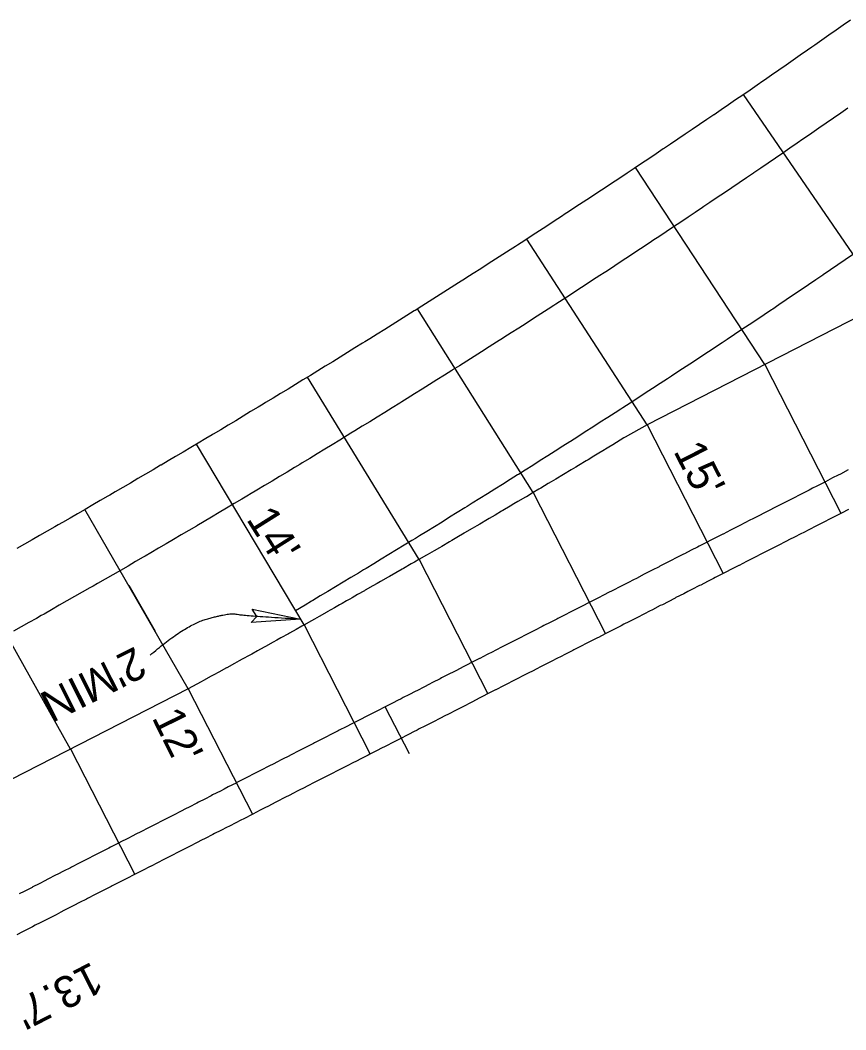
# Model space of a CAD drawing. Extents: x 2145147 to 2158018, y 137519 to 148068.
# Drawn here: x 2149689.7 to 2149783.3, y 143167.4 to 143282 of the extents above; entities that cross this region are included whole.
import ezdxf

# ---------------------------------------------------------------- set-up
doc = ezdxf.new("R2010")
doc.units = 0
for name, color, linetype in [('PR_Align_Ramp_A', 7, 'Continuous'), ('PR_Align_Ramp_F', 7, 'Continuous'), ('PR_Dimensions', 7, 'Continuous'), ('PR_Joint_Contraction', 7, 'Continuous'), ('PR_Joint_Long', 7, 'Continuous'), ('PR_Road_Concrete', 7, 'Continuous')]:
    doc.layers.add(name, color=color, linetype=linetype)

msp = doc.modelspace()

# ---------------------------------------------------------------- linework, layer by layer
at = {"layer": 'PR_Align_Ramp_A'}
msp.add_lwpolyline([(2149733.83, 143198.72), (2149731.09, 143204.07)], dxfattribs=at)
at = {"layer": 'PR_Align_Ramp_F'}
msp.add_lwpolyline([(2149705.04, 143212.62), (2149702.04, 143217.81)], dxfattribs=at)
at = {"layer": 'PR_Dimensions'}
msp.add_lwpolyline([(2149721.48, 143214.02), (2149715.88, 143213.61), (2149716.51, 143214.32), (2149715.99, 143215.14)], close=True, dxfattribs=at)
msp.add_open_spline([(2149704.41, 143209.91), (2149708.45, 143213.4), (2149713.52, 143214.74), (2149714.67, 143214.44), (2149721.48, 143214.02)], degree=2, dxfattribs=at)
at = {"layer": 'PR_Joint_Contraction'}
for p, q in [((2149785.87, 143252.94), (2149771.73, 143273.55)), ((2149774.15, 143242.92), (2149759.48, 143265.26)), ((2149760.8, 143236.08), (2149747.15, 143257.15)), ((2149747.89, 143228.38), (2149734.75, 143249.23)), ((2149774.15, 143242.92), (2149782.79, 143226.02)), ((2149734.93, 143220.78), (2149722.26, 143241.47)), ((2149760.8, 143236.08), (2149769.44, 143219.19)), ((2149721.88, 143213.35), (2149709.68, 143233.87)), ((2149747.89, 143228.38), (2149756.09, 143212.36)), ((2149708.74, 143206.1), (2149697, 143226.45)), ((2149734.93, 143220.78), (2149742.73, 143205.53)), ((2149695.38, 143199.26), (2149684.22, 143219.18)), ((2149721.88, 143213.35), (2149729.38, 143198.69)), ((2149708.74, 143206.1), (2149716.02, 143191.86)), ((2149695.39, 143199.27), (2149702.67, 143185.03))]:
    msp.add_line(p, q, dxfattribs=at)
at = {"layer": 'PR_Joint_Long'}
msp.add_line((2149708.74, 143206.1), (2149656.52, 143179.39), dxfattribs=at)
for points in [[(2149783.57, 143272.02), (2149782.76, 143271.44), (2149781.94, 143270.87), (2149781.12, 143270.31), (2149780.3, 143269.74), (2149779.47, 143269.17), (2149778.65, 143268.6), (2149778.48, 143268.48), (2149777.83, 143268.04), (2149777.01, 143267.47), (2149776.19, 143266.9), (2149775.36, 143266.34), (2149774.54, 143265.78), (2149773.71, 143265.21), (2149772.89, 143264.65), (2149772.87, 143264.64), (2149772.06, 143264.09), (2149771.24, 143263.53), (2149770.41, 143262.97), (2149769.58, 143262.41), (2149768.76, 143261.85), (2149767.93, 143261.29), (2149767.24, 143260.83), (2149767.1, 143260.74), (2149766.27, 143260.18), (2149765.44, 143259.62), (2149764.61, 143259.07), (2149763.78, 143258.52), (2149762.95, 143257.96), (2149762.12, 143257.41), (2149761.58, 143257.05), (2149761.29, 143256.86), (2149760.46, 143256.31), (2149759.62, 143255.76), (2149758.79, 143255.21), (2149757.96, 143254.66), (2149757.12, 143254.11), (2149756.29, 143253.56), (2149755.91, 143253.31), (2149755.45, 143253.01), (2149754.62, 143252.47), (2149753.78, 143251.92), (2149752.94, 143251.38), (2149752.11, 143250.83), (2149751.27, 143250.29), (2149750.86, 143250.02), (2149750.43, 143249.75), (2149750.21, 143249.6), (2149749.59, 143249.21), (2149748.75, 143248.66), (2149747.92, 143248.12), (2149747.08, 143247.58), (2149746.24, 143247.05), (2149745.39, 143246.51), (2149744.55, 143245.97), (2149744.49, 143245.93), (2149743.71, 143245.43), (2149742.87, 143244.9), (2149742.03, 143244.36), (2149741.18, 143243.83), (2149740.34, 143243.29), (2149739.5, 143242.76), (2149738.74, 143242.29), (2149738.65, 143242.23), (2149737.81, 143241.7), (2149736.96, 143241.17), (2149736.12, 143240.64), (2149735.27, 143240.11), (2149734.42, 143239.58), (2149733.57, 143239.05), (2149732.98, 143238.68), (2149732.73, 143238.52), (2149731.88, 143238), (2149731.03, 143237.47), (2149730.18, 143236.95), (2149729.33, 143236.42), (2149728.48, 143235.9), (2149727.63, 143235.38), (2149727.2, 143235.11), (2149726.78, 143234.85), (2149725.93, 143234.33), (2149725.08, 143233.81), (2149724.22, 143233.29), (2149723.37, 143232.77), (2149722.52, 143232.26), (2149721.66, 143231.74), (2149721.39, 143231.57), (2149720.81, 143231.22), (2149719.96, 143230.71), (2149719.1, 143230.19), (2149718.25, 143229.68), (2149717.39, 143229.16), (2149716.53, 143228.65), (2149715.68, 143228.14), (2149715.56, 143228.07), (2149714.82, 143227.63), (2149713.96, 143227.12), (2149713.1, 143226.61), (2149712.24, 143226.1), (2149711.39, 143225.59), (2149710.53, 143225.08), (2149709.72, 143224.6), (2149709.67, 143224.57), (2149708.81, 143224.07), (2149707.95, 143223.56), (2149707.08, 143223.06), (2149706.22, 143222.55), (2149705.36, 143222.05), (2149704.5, 143221.55), (2149703.85, 143221.17), (2149703.63, 143221.04), (2149702.77, 143220.54), (2149701.91, 143220.04), (2149701.04, 143219.54), (2149700.18, 143219.05), (2149699.31, 143218.55), (2149698.45, 143218.05), (2149697.96, 143217.77), (2149697.58, 143217.55), (2149696.71, 143217.06), (2149695.85, 143216.56), (2149694.98, 143216.07), (2149694.11, 143215.58), (2149693.24, 143215.08), (2149692.38, 143214.59), (2149692.05, 143214.41), (2149691.51, 143214.1), (2149690.64, 143213.61), (2149689.77, 143213.12), (2149688.9, 143212.63)], [(2149784.1, 143255.36), (2149783.27, 143254.79), (2149782.44, 143254.22), (2149781.6, 143253.65), (2149780.77, 143253.08), (2149780.74, 143253.06), (2149779.93, 143252.51), (2149779.1, 143251.94), (2149778.26, 143251.38), (2149777.42, 143250.81), (2149776.58, 143250.25), (2149775.75, 143249.68), (2149775.05, 143249.21), (2149774.91, 143249.12), (2149774.07, 143248.55), (2149773.23, 143247.99), (2149772.39, 143247.43), (2149771.55, 143246.87), (2149770.71, 143246.31), (2149769.87, 143245.75), (2149769.32, 143245.39), (2149769.02, 143245.19), (2149768.18, 143244.63), (2149767.34, 143244.07), (2149766.5, 143243.52), (2149765.65, 143242.96), (2149764.81, 143242.41), (2149763.96, 143241.85), (2149763.58, 143241.6), (2149763.12, 143241.3), (2149762.27, 143240.75), (2149761.43, 143240.19), (2149760.58, 143239.64), (2149759.73, 143239.09), (2149758.89, 143238.54), (2149758.47, 143238.27), (2149758.04, 143237.99), (2149757.81, 143237.84), (2149757.19, 143237.44), (2149756.34, 143236.9), (2149755.49, 143236.35), (2149754.64, 143235.8), (2149753.79, 143235.26), (2149752.94, 143234.71), (2149752.09, 143234.17), (2149752.02, 143234.12), (2149751.23, 143233.63), (2149750.38, 143233.08), (2149749.53, 143232.54), (2149748.67, 143232), (2149747.82, 143231.46), (2149746.97, 143230.92), (2149746.21, 143230.44), (2149746.11, 143230.38), (2149745.26, 143229.84), (2149744.4, 143229.31), (2149743.54, 143228.77), (2149742.69, 143228.23), (2149741.83, 143227.7), (2149740.97, 143227.17), (2149740.37, 143226.79), (2149740.11, 143226.63), (2149739.26, 143226.1), (2149738.4, 143225.57), (2149737.54, 143225.03), (2149736.68, 143224.5), (2149735.82, 143223.97), (2149734.96, 143223.45), (2149734.52, 143223.18), (2149734.09, 143222.92), (2149733.23, 143222.39), (2149732.37, 143221.86), (2149731.51, 143221.34), (2149730.64, 143220.81), (2149729.78, 143220.29), (2149728.92, 143219.76), (2149728.64, 143219.59), (2149728.05, 143219.24), (2149727.19, 143218.72), (2149726.32, 143218.2), (2149725.46, 143217.68), (2149724.59, 143217.16), (2149723.72, 143216.64), (2149722.86, 143216.12), (2149722.74, 143216.05), (2149721.99, 143215.6), (2149720.92, 143214.96)], [(2149797.26, 143254.77), (2149760.8, 143236.08)], [(2149760.8, 143236.08), (2149758.3, 143234.66), (2149758.17, 143234.58), (2149757.31, 143234.05), (2149756.9, 143233.81), (2149756.46, 143233.53), (2149755.6, 143233.01), (2149755.51, 143232.96), (2149754.74, 143232.49), (2149754.11, 143232.11), (2149753.88, 143231.98), (2149753.02, 143231.46), (2149752.71, 143231.27), (2149752.17, 143230.94), (2149751.31, 143230.43), (2149750.45, 143229.91), (2149749.9, 143229.59), (2149749.59, 143229.4), (2149748.73, 143228.88), (2149748.5, 143228.75), (2149747.87, 143228.37), (2149747.1, 143227.91), (2149747, 143227.86), (2149746.14, 143227.35), (2149745.69, 143227.08), (2149745.28, 143226.84), (2149744.42, 143226.33), (2149744.28, 143226.25), (2149743.55, 143225.82), (2149742.88, 143225.42), (2149742.69, 143225.31), (2149741.83, 143224.8), (2149741.47, 143224.59), (2149740.96, 143224.3), (2149740.1, 143223.79), (2149740.06, 143223.77), (2149739.23, 143223.28), (2149738.65, 143222.94), (2149738.37, 143222.78), (2149737.5, 143222.27), (2149737.24, 143222.12), (2149736.64, 143221.77), (2149735.83, 143221.3), (2149735.77, 143221.27), (2149734.9, 143220.77), (2149734.41, 143220.48), (2149734.04, 143220.27), (2149733.17, 143219.77), (2149733, 143219.67), (2149732.3, 143219.27), (2149731.58, 143218.86), (2149731.43, 143218.77), (2149730.56, 143218.27), (2149730.17, 143218.05), (2149729.7, 143217.78), (2149728.83, 143217.28), (2149728.75, 143217.24), (2149727.96, 143216.79), (2149727.33, 143216.43), (2149727.09, 143216.29), (2149726.71, 143216.08), (2149726.21, 143215.8), (2149725.91, 143215.62), (2149725.34, 143215.3), (2149724.49, 143214.82), (2149724.47, 143214.81), (2149723.6, 143214.32), (2149723.06, 143214.02), (2149722.73, 143213.83), (2149721.86, 143213.34), (2149721.64, 143213.22), (2149720.98, 143212.85), (2149720.22, 143212.42), (2149720.11, 143212.36), (2149719.23, 143211.88), (2149718.79, 143211.63), (2149718.36, 143211.39), (2149717.49, 143210.9), (2149717.37, 143210.84), (2149716.61, 143210.42), (2149715.94, 143210.05), (2149715.74, 143209.93), (2149714.86, 143209.45), (2149714.51, 143209.26), (2149713.98, 143208.97), (2149713.11, 143208.49), (2149713.08, 143208.47), (2149712.23, 143208), (2149711.65, 143207.69), (2149711.35, 143207.52), (2149710.47, 143207.04), (2149710.22, 143206.9), (2149708.74, 143206.1)], [(2149783.62, 143230.94), (2149782.73, 143230.48), (2149782.48, 143230.36), (2149781.84, 143230.03), (2149781.03, 143229.61), (2149780.95, 143229.57), (2149780.06, 143229.12), (2149779.58, 143228.87), (2149779.17, 143228.66), (2149778.28, 143228.2), (2149778.13, 143228.13), (2149777.39, 143227.75), (2149776.67, 143227.38), (2149776.5, 143227.29), (2149775.61, 143226.84), (2149775.22, 143226.64), (2149774.72, 143226.38), (2149773.83, 143225.93), (2149773.77, 143225.9), (2149772.94, 143225.47), (2149772.32, 143225.16), (2149772.05, 143225.02), (2149771.16, 143224.56), (2149770.87, 143224.41), (2149770.27, 143224.11), (2149769.42, 143223.67), (2149769.38, 143223.65), (2149768.48, 143223.19), (2149767.96, 143222.93), (2149767.6, 143222.74), (2149766.93, 143222.4), (2149766.71, 143222.28), (2149766.51, 143222.19), (2149765.81, 143221.83), (2149765.06, 143221.44), (2149764.92, 143221.37), (2149764.03, 143220.92), (2149763.61, 143220.7), (2149763.14, 143220.46), (2149762.25, 143220.01), (2149762.16, 143219.96), (2149761.36, 143219.55), (2149760.71, 143219.21), (2149760.47, 143219.1), (2149759.58, 143218.64), (2149759.25, 143218.47), (2149758.69, 143218.18), (2149757.8, 143217.73), (2149756.91, 143217.27), (2149756.35, 143216.99), (2149756.02, 143216.82), (2149755.13, 143216.36), (2149754.9, 143216.24), (2149754.24, 143215.91), (2149753.45, 143215.5), (2149753.35, 143215.45), (2149752.46, 143215), (2149751.99, 143214.76), (2149751.57, 143214.54), (2149750.68, 143214.09), (2149750.54, 143214.02), (2149749.79, 143213.63), (2149749.09, 143213.27), (2149748.9, 143213.17), (2149748.01, 143212.72), (2149747.64, 143212.53), (2149747.12, 143212.26), (2149746.23, 143211.81), (2149746.19, 143211.79), (2149745.34, 143211.35), (2149744.74, 143211.05), (2149744.45, 143210.9), (2149743.56, 143210.44), (2149743.28, 143210.3), (2149742.67, 143209.99), (2149741.83, 143209.56), (2149741.78, 143209.53), (2149740.89, 143209.08), (2149740.38, 143208.82), (2149740, 143208.62), (2149739.11, 143208.16), (2149738.93, 143208.07), (2149738.22, 143207.71), (2149737.48, 143207.33), (2149737.33, 143207.25), (2149736.44, 143206.8), (2149736.03, 143206.59), (2149735.55, 143206.34), (2149734.66, 143205.89), (2149734.57, 143205.85), (2149733.76, 143205.43), (2149733.12, 143205.1), (2149732.88, 143204.98), (2149732.49, 143204.78), (2149731.98, 143204.52), (2149731.67, 143204.36), (2149731.1, 143204.07), (2149730.22, 143203.62), (2149730.2, 143203.61), (2149729.31, 143203.15), (2149728.77, 143202.88), (2149728.42, 143202.7), (2149727.53, 143202.24), (2149727.32, 143202.13), (2149726.64, 143201.79), (2149725.86, 143201.39), (2149725.75, 143201.33), (2149724.86, 143200.88), (2149724.41, 143200.65), (2149723.97, 143200.42), (2149723.08, 143199.97), (2149722.96, 143199.9), (2149722.19, 143199.51), (2149721.51, 143199.16), (2149721.3, 143199.05), (2149720.41, 143198.6), (2149720.06, 143198.42), (2149719.52, 143198.14), (2149718.63, 143197.69), (2149718.6, 143197.68), (2149717.74, 143197.23), (2149717.15, 143196.93), (2149716.85, 143196.78), (2149715.96, 143196.32), (2149715.7, 143196.19), (2149715.07, 143195.87), (2149714.25, 143195.45), (2149714.18, 143195.41), (2149713.29, 143194.96), (2149712.8, 143194.7), (2149712.4, 143194.5), (2149711.51, 143194.05), (2149711.35, 143193.96), (2149710.62, 143193.59), (2149709.9, 143193.22), (2149709.73, 143193.13), (2149708.84, 143192.68), (2149708.44, 143192.48), (2149707.95, 143192.22), (2149707.06, 143191.77), (2149706.99, 143191.73), (2149706.17, 143191.31), (2149705.54, 143190.99), (2149705.28, 143190.86), (2149704.39, 143190.4), (2149704.09, 143190.25), (2149703.5, 143189.95), (2149702.64, 143189.51), (2149702.61, 143189.49), (2149701.72, 143189.04), (2149701.18, 143188.76), (2149700.83, 143188.58), (2149699.94, 143188.12), (2149699.73, 143188.02), (2149699.05, 143187.67), (2149698.28, 143187.28), (2149698.15, 143187.21), (2149697.26, 143186.76), (2149696.83, 143186.54), (2149696.38, 143186.3), (2149695.48, 143185.85), (2149695.38, 143185.79), (2149694.59, 143185.39), (2149693.93, 143185.05), (2149693.7, 143184.94), (2149692.81, 143184.48), (2149692.47, 143184.31), (2149691.92, 143184.02), (2149691.03, 143183.57), (2149691.02, 143183.56), (2149690.14, 143183.11), (2149689.57, 143182.82)]]:
    msp.add_lwpolyline(points, dxfattribs=at)
at = {"layer": 'PR_Road_Concrete'}
for points in [[(2149783.87, 143281.99), (2149783.06, 143281.42), (2149782.25, 143280.85), (2149781.43, 143280.28), (2149780.62, 143279.71), (2149779.81, 143279.14), (2149779.48, 143278.92), (2149779, 143278.58), (2149778.18, 143278.01), (2149777.37, 143277.44), (2149776.56, 143276.88), (2149775.74, 143276.31), (2149774.93, 143275.75), (2149774.11, 143275.19), (2149773.93, 143275.07), (2149773.29, 143274.62), (2149772.48, 143274.06), (2149771.66, 143273.5), (2149770.84, 143272.94), (2149770.02, 143272.38), (2149769.21, 143271.82), (2149768.39, 143271.26), (2149768.37, 143271.25), (2149767.57, 143270.71), (2149766.75, 143270.15), (2149765.93, 143269.59), (2149765.1, 143269.04), (2149764.28, 143268.48), (2149763.46, 143267.93), (2149762.77, 143267.47), (2149762.64, 143267.38), (2149761.82, 143266.82), (2149760.99, 143266.27), (2149760.17, 143265.72), (2149759.34, 143265.17), (2149758.52, 143264.62), (2149757.69, 143264.07), (2149757.16, 143263.72), (2149756.87, 143263.53), (2149756.04, 143262.98), (2149755.21, 143262.43), (2149754.39, 143261.88), (2149753.56, 143261.34), (2149752.73, 143260.8), (2149751.9, 143260.25), (2149751.52, 143260), (2149751.07, 143259.71), (2149750.24, 143259.17), (2149749.41, 143258.62), (2149748.58, 143258.08), (2149747.75, 143257.54), (2149746.92, 143257), (2149746.51, 143256.74), (2149746.09, 143256.46), (2149745.86, 143256.32), (2149745.25, 143255.93), (2149744.42, 143255.39), (2149743.59, 143254.85), (2149742.75, 143254.32), (2149741.92, 143253.78), (2149741.08, 143253.25), (2149740.25, 143252.71), (2149740.18, 143252.67), (2149739.41, 143252.18), (2149738.58, 143251.65), (2149737.74, 143251.12), (2149736.9, 143250.59), (2149736.07, 143250.06), (2149735.23, 143249.53), (2149734.48, 143249.06), (2149734.39, 143249), (2149733.55, 143248.47), (2149732.71, 143247.94), (2149731.87, 143247.42), (2149731.03, 143246.89), (2149730.19, 143246.37), (2149729.35, 143245.84), (2149728.76, 143245.48), (2149728.51, 143245.32), (2149727.66, 143244.8), (2149726.82, 143244.27), (2149725.98, 143243.75), (2149725.13, 143243.23), (2149724.29, 143242.71), (2149723.45, 143242.19), (2149723.01, 143241.93), (2149722.6, 143241.68), (2149721.75, 143241.16), (2149720.91, 143240.64), (2149720.06, 143240.13), (2149719.22, 143239.61), (2149718.37, 143239.1), (2149717.52, 143238.58), (2149717.25, 143238.42), (2149716.67, 143238.07), (2149715.82, 143237.56), (2149714.98, 143237.04), (2149714.13, 143236.53), (2149713.28, 143236.02), (2149712.43, 143235.51), (2149711.57, 143235.01), (2149711.46, 143234.94), (2149710.72, 143234.5), (2149709.87, 143233.99), (2149709.02, 143233.48), (2149708.17, 143232.98), (2149707.31, 143232.47), (2149706.46, 143231.97), (2149705.66, 143231.49), (2149705.61, 143231.47), (2149704.75, 143230.96), (2149703.9, 143230.46), (2149703.04, 143229.96), (2149702.19, 143229.46), (2149701.33, 143228.96), (2149700.47, 143228.46), (2149699.83, 143228.09), (2149699.62, 143227.96), (2149698.76, 143227.47), (2149697.9, 143226.97), (2149697.04, 143226.47), (2149696.18, 143225.98), (2149695.33, 143225.48), (2149694.47, 143224.99), (2149693.98, 143224.71), (2149693.61, 143224.5), (2149692.75, 143224), (2149691.88, 143223.51), (2149691.02, 143223.02), (2149690.16, 143222.53), (2149689.3, 143222.04)], [(2149783.66, 143226.47), (2149782.85, 143226.05), (2149782.77, 143226.01), (2149781.88, 143225.55), (2149781.4, 143225.31), (2149780.99, 143225.1), (2149780.1, 143224.64), (2149779.95, 143224.57), (2149779.21, 143224.19), (2149778.5, 143223.82), (2149778.32, 143223.73), (2149777.43, 143223.28), (2149777.04, 143223.08), (2149776.54, 143222.82), (2149775.65, 143222.37), (2149775.59, 143222.34), (2149774.76, 143221.91), (2149774.14, 143221.6), (2149773.87, 143221.46), (2149772.98, 143221), (2149772.69, 143220.85), (2149772.09, 143220.55), (2149771.24, 143220.11), (2149771.2, 143220.09), (2149770.31, 143219.63), (2149769.79, 143219.37), (2149769.42, 143219.18), (2149768.75, 143218.84), (2149768.53, 143218.72), (2149768.33, 143218.62), (2149767.64, 143218.27), (2149766.88, 143217.88), (2149766.75, 143217.81), (2149765.86, 143217.36), (2149765.43, 143217.14), (2149764.97, 143216.9), (2149764.07, 143216.45), (2149763.98, 143216.4), (2149763.19, 143215.99), (2149762.53, 143215.65), (2149762.29, 143215.54), (2149761.4, 143215.08), (2149761.08, 143214.91), (2149760.51, 143214.62), (2149759.62, 143214.17), (2149758.73, 143213.71), (2149758.17, 143213.43), (2149757.84, 143213.26), (2149756.95, 143212.8), (2149756.72, 143212.68), (2149756.06, 143212.35), (2149755.27, 143211.94), (2149755.17, 143211.89), (2149754.28, 143211.44), (2149753.82, 143211.2), (2149753.39, 143210.98), (2149752.5, 143210.52), (2149752.37, 143210.45), (2149751.61, 143210.07), (2149750.91, 143209.71), (2149750.72, 143209.61), (2149749.83, 143209.16), (2149749.46, 143208.97), (2149748.94, 143208.7), (2149748.05, 143208.25), (2149748.01, 143208.23), (2149747.16, 143207.79), (2149746.56, 143207.48), (2149746.27, 143207.34), (2149745.38, 143206.88), (2149745.11, 143206.74), (2149744.49, 143206.43), (2149743.65, 143206), (2149743.6, 143205.97), (2149742.71, 143205.52), (2149742.2, 143205.26), (2149741.82, 143205.06), (2149740.93, 143204.6), (2149740.75, 143204.51), (2149740.04, 143204.15), (2149739.3, 143203.77), (2149739.15, 143203.69), (2149738.26, 143203.24), (2149737.85, 143203.03), (2149737.37, 143202.78), (2149736.48, 143202.33), (2149736.4, 143202.29), (2149735.59, 143201.87), (2149734.94, 143201.54), (2149734.7, 143201.41), (2149734.31, 143201.22), (2149733.81, 143200.96), (2149733.49, 143200.8), (2149732.92, 143200.5), (2149732.04, 143200.06), (2149732.03, 143200.05), (2149731.14, 143199.59), (2149730.59, 143199.31), (2149730.25, 143199.14), (2149729.35, 143198.68), (2149729.14, 143198.57), (2149728.46, 143198.23), (2149727.69, 143197.83), (2149727.57, 143197.77), (2149726.69, 143197.32), (2149726.23, 143197.09), (2149725.79, 143196.86), (2149724.9, 143196.4), (2149724.78, 143196.34), (2149724.01, 143195.95), (2149723.33, 143195.6), (2149723.12, 143195.49), (2149722.23, 143195.04), (2149721.88, 143194.86), (2149721.34, 143194.58), (2149720.45, 143194.13), (2149720.43, 143194.11), (2149719.56, 143193.67), (2149718.97, 143193.37), (2149718.67, 143193.22), (2149717.78, 143192.76), (2149717.52, 143192.63), (2149716.89, 143192.31), (2149716.07, 143191.89), (2149716, 143191.85), (2149715.11, 143191.39), (2149714.62, 143191.14), (2149714.22, 143190.94), (2149713.33, 143190.48), (2149713.17, 143190.4), (2149712.44, 143190.03), (2149711.72, 143189.66), (2149711.55, 143189.57), (2149710.66, 143189.12), (2149710.26, 143188.92), (2149709.77, 143188.66), (2149708.88, 143188.21), (2149708.81, 143188.17), (2149707.99, 143187.75), (2149707.36, 143187.43), (2149707.1, 143187.3), (2149706.21, 143186.84), (2149705.91, 143186.69), (2149705.32, 143186.38), (2149704.46, 143185.94), (2149704.43, 143185.93), (2149703.54, 143185.47), (2149703.01, 143185.2), (2149702.65, 143185.02), (2149701.76, 143184.56), (2149701.55, 143184.46), (2149700.87, 143184.11), (2149700.1, 143183.72), (2149699.98, 143183.65), (2149699.09, 143183.2), (2149698.65, 143182.97), (2149698.2, 143182.74), (2149697.31, 143182.29), (2149697.2, 143182.23), (2149696.42, 143181.83), (2149695.75, 143181.49), (2149695.53, 143181.38), (2149694.64, 143180.92), (2149694.3, 143180.75), (2149693.74, 143180.46), (2149692.85, 143180.01), (2149692.84, 143180), (2149691.96, 143179.55), (2149691.39, 143179.26), (2149691.07, 143179.1), (2149690.18, 143178.64), (2149689.94, 143178.52), (2149689.29, 143178.19)]]:
    msp.add_lwpolyline(points, dxfattribs=at)

# ---------------------------------------------------------------- texts
at = {"layer": 'PR_Dimensions'}
for s, rotation, p in [("15'", 296.9637, (2149763.74, 143233.08)), ("14'", 302.1973, (2149715.26, 143225.36)), ("2'MIN", 206.6406, (2149702.74, 143210.97)), ("12'", 296.3314, (2149704.56, 143202.84)), ("13.7'", 207.0429, (2149697.82, 143175.17))]:
    msp.add_text(s, height=3.6, rotation=rotation, dxfattribs=at).set_placement(p)

doc.saveas('drawing.dxf')
